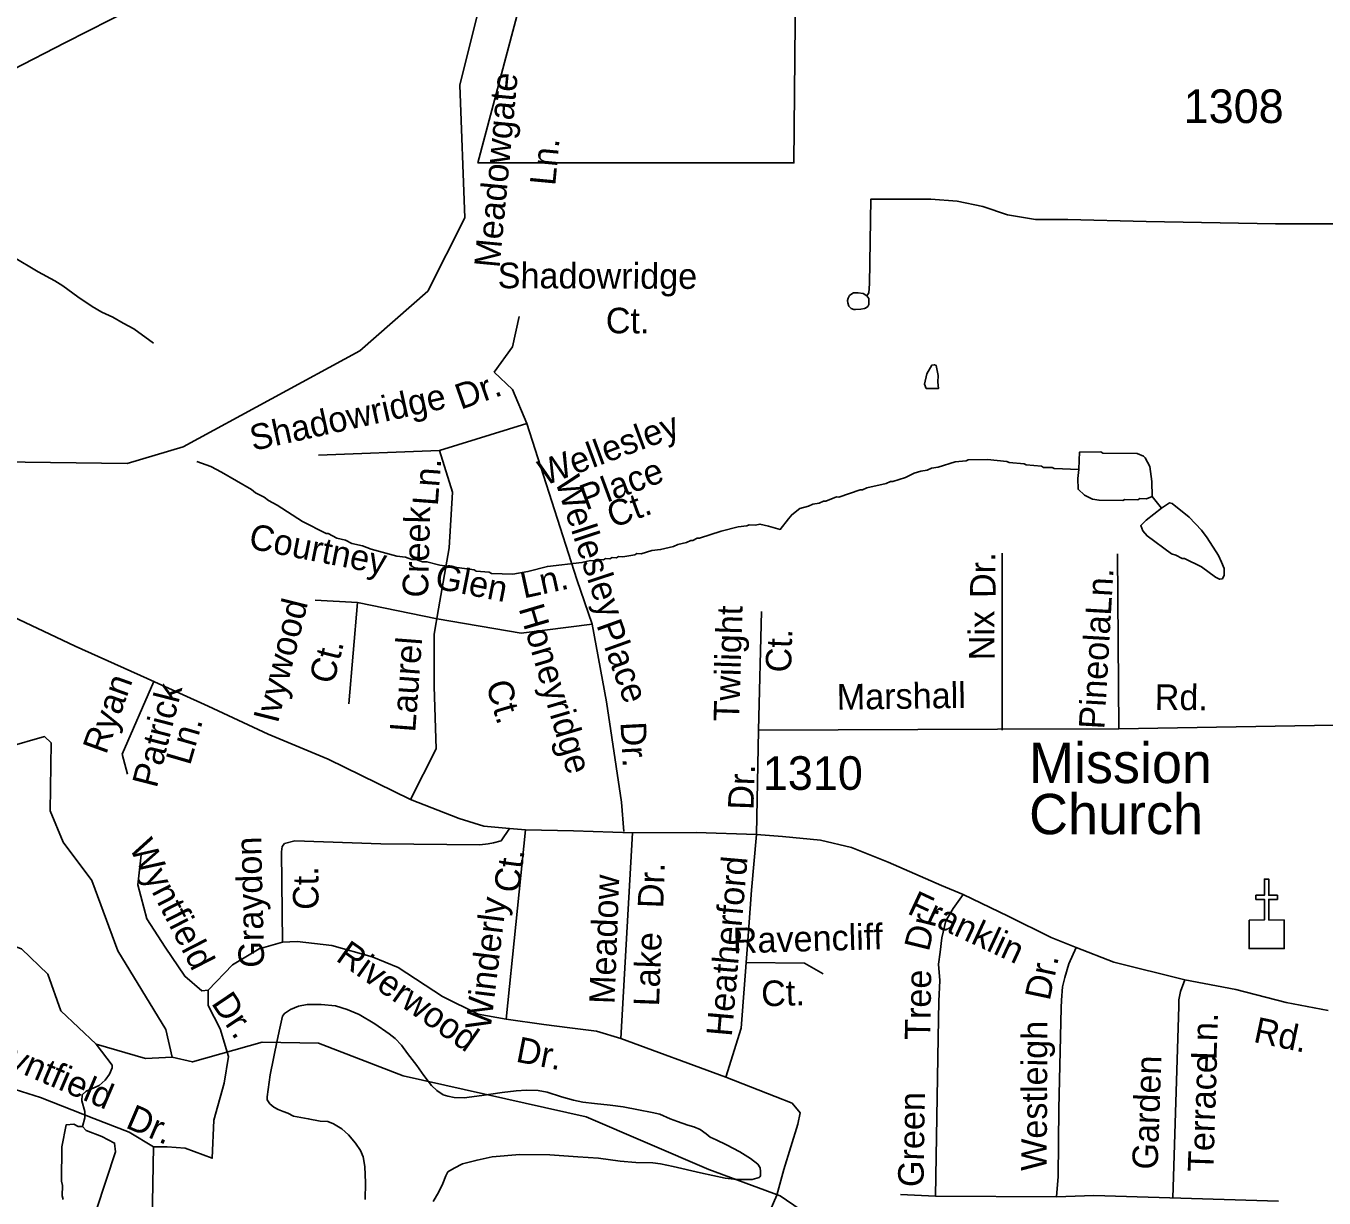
# Model space of a CAD drawing. Extents: x 1547597 to 1699558, y 810033 to 920809.
# Drawn here: x 1580417 to 1585242, y 862123 to 866479 of the extents above; entities that cross this region are included whole.
import ezdxf

# ---------------------------------------------------------------- set-up
doc = ezdxf.new("R2010")
doc.units = 0
for name, color, linetype in [('Exist Boundary Political City Limit New Hole', 7, 'Continuous'), ('Exist Cultural Church CELL', 7, 'Continuous'), ('Exist Cultural Church Label', 7, 'Continuous'), ('Exist Hydrographic Creek Single Shore', 7, 'Continuous'), ('Exist Hydrographic Misc Water Feature', 7, 'Continuous'), ('Exist Hydrographic Pond Under 1500 Sq Ft', 7, 'Continuous'), ('Exist Road Non-System Type 51', 7, 'Continuous'), ('Exist Road Non-System Type 51 Label', 7, 'Continuous'), ('Exist Road Secondary Type 51 Attributed', 7, 'Continuous'), ('Exist Road Secondary Type 51 Label', 7, 'Continuous'), ('Exist Road Secondary Type 51 Number Label', 7, 'Continuous')]:
    doc.layers.add(name, color=color, linetype=linetype)

msp = doc.modelspace()

# ---------------------------------------------------------------- linework, layer by layer
at = {"layer": 'Exist Boundary Political City Limit New Hole'}
msp.add_lwpolyline([(1583517.5, 866753.2), (1583718.2, 867614.8), (1582814.9, 868112.4), (1582523, 867797.8), (1582463.1, 867408.2), (1582530.5, 867385.8), (1582530.5, 867333.3), (1582515.5, 867265.9), (1582463.1, 867235.9), (1582418.2, 867183.5), (1582096.3, 865969.9), (1583271.4, 865969.9), (1583277.9, 866753.2), (1583517.5, 866753.2)], dxfattribs=at)
at = {"layer": 'Exist Cultural Church CELL'}
msp.add_lwpolyline([(1584963.4, 863156.3), (1585020.4, 863156.4), (1585020.4, 863232.6), (1584988.4, 863232.6), (1584988.4, 863248.5), (1585020.4, 863248.5), (1585020.4, 863308.7), (1585036.4, 863308.7), (1585036.4, 863248.5), (1585068.4, 863248.5), (1585068.4, 863232.6), (1585036.4, 863232.6), (1585036.4, 863156.4), (1585094.1, 863156.3), (1585094.1, 863049.8), (1584963.4, 863049.8)], close=True, dxfattribs=at)
at = {"layer": 'Exist Hydrographic Creek Single Shore'}
msp.add_lwpolyline([(1579810.6, 865007.4), (1580317.5, 864859.2), (1580792.5, 864852.9), (1581001.5, 864914.3), (1581657.6, 865271.9), (1581910.5, 865493.4), (1582047.6, 865766.4), (1582029.5, 866259.1), (1582100.5, 866543.2), (1582328.5, 866722.6), (1582521.5, 866810.5), (1582798.6, 866932.9), (1583185.5, 867210.7), (1583297.4, 867418.6)], dxfattribs=at)
at = {"layer": 'Exist Hydrographic Misc Water Feature'}
msp.add_line((1584637.3, 864686.5), (1584602.6, 864730.5), dxfattribs=at)
for points in [[(1583763.4, 865132), (1583794.4, 865131.7), (1583808.6, 865131.5), (1583806.7, 865155.4), (1583807, 865179.4), (1583799.4, 865217.6), (1583793.5, 865219.6), (1583783.4, 865217.8), (1583765.1, 865186), (1583756.7, 865148.2), (1583763.4, 865132)], [(1584602.6, 864730.5), (1584602.2, 864785.6), (1584594.8, 864841.7), (1584577.2, 864873.9), (1584571.3, 864880), (1584547.5, 864890.3), (1584419.5, 864891.8), (1584411.5, 864895.9), (1584332.2, 864894.8), (1584331.1, 864865), (1584330.1, 864830.6)], [(1584330.1, 864830.6), (1584238.9, 864834.2), (1584230.9, 864838.2), (1584198.9, 864838.6), (1584191, 864842.7), (1584135, 864847.5), (1584127.1, 864851.6), (1584071.1, 864856.3), (1584063.1, 864860.4), (1583991.3, 864867.2), (1583919.3, 864866.2), (1583911.2, 864862.3), (1583871.2, 864858.8), (1583807, 864839.7), (1583782.9, 864835.9), (1583766.8, 864828.1), (1583742.8, 864824.4), (1583718.7, 864816.7), (1583686.5, 864801.1), (1583638.4, 864785.7), (1583630.4, 864785.8), (1583614.3, 864778), (1583542.1, 864763), (1583526, 864755.2), (1583518, 864755.3), (1583437.7, 864728.3), (1583429.7, 864728.4), (1583389.5, 864712.9), (1583381.5, 864713), (1583365.4, 864705.3), (1583341.4, 864701.6), (1583325.3, 864693.8), (1583293.3, 864686.2), (1583263, 864662.5), (1583250.8, 864646.7), (1583220.5, 864608.1), (1583176.5, 864619.6), (1583144.6, 864628), (1583128.6, 864624.3), (1583104.6, 864624.6), (1583096.5, 864620.7), (1583064.5, 864617.1), (1583000.3, 864601.9), (1582920, 864574.9), (1582912, 864574.9), (1582896, 864567.1), (1582888, 864567.3), (1582871.9, 864559.5), (1582839.8, 864551.9), (1582823.7, 864544.1), (1582775.5, 864532.7), (1582743.5, 864529.1), (1582703.3, 864517.6), (1582687.3, 864517.8), (1582679.3, 864513.9), (1582635.2, 864506.5), (1582619.3, 864506.7), (1582611.3, 864502.8), (1582595.3, 864503), (1582587.2, 864499.1), (1582571.2, 864499.3), (1582563.2, 864495.4), (1582547.2, 864495.6), (1582539.1, 864491.7), (1582515.1, 864492), (1582483, 864484.4), (1582354.8, 864470.1), (1582282.7, 864451), (1582226.6, 864441.7), (1582146.6, 864444.6), (1582138.7, 864448.7), (1582090.7, 864453.3), (1582082.7, 864457.4), (1581955, 864475.1), (1581907.2, 864487.7), (1581891.2, 864487.9), (1581867.3, 864496.2), (1581851.3, 864496.4), (1581827.3, 864504.7), (1581795.5, 864509.1), (1581699.8, 864534.2), (1581667.9, 864546.6), (1581628, 864555.2), (1581604.1, 864567.5), (1581572.3, 864575.9), (1581540.5, 864592.3), (1581532.5, 864592.4), (1581445, 864637.4), (1581349.8, 864698.6), (1581318, 864715), (1581302.1, 864727.2), (1581270.3, 864743.6), (1581254.5, 864755.8), (1581143.3, 864821.1), (1581103.5, 864841.6), (1581051.4, 864860.3)], [(1584330.1, 864830.6), (1584326.4, 864797.1), (1584327.8, 864757.1), (1584351.6, 864734.8), (1584381.5, 864720.4), (1584405.4, 864716.1), (1584493.3, 864715), (1584501.4, 864718.9), (1584549.4, 864718.3), (1584557.4, 864722.2), (1584581.4, 864722), (1584602.6, 864730.5)], [(1584637.3, 864686.5), (1584667.2, 864706.8), (1584677.2, 864704.7), (1584740.6, 864654), (1584786, 864605.4), (1584807.7, 864577.1), (1584848.9, 864510.7), (1584860.6, 864486.5), (1584870.3, 864462.4), (1584870, 864438.4), (1584863.9, 864424.5), (1584853.8, 864422.6), (1584837.9, 864430.8), (1584786.3, 864469.4), (1584722.8, 864500.2), (1584714.8, 864500.3), (1584690.9, 864512.6), (1584675, 864516.8), (1584583.8, 864584), (1584568, 864602.1), (1584560.3, 864622.2), (1584580.5, 864642), (1584637.3, 864686.5)], [(1581350.6, 862708.5), (1581360.1, 862754.5), (1581370, 862799.4), (1581377.1, 862809.2), (1581399.4, 862823.9), (1581429.7, 862836.4), (1581461.8, 862841.8), (1581514, 862841.8), (1581567, 862836.9), (1581610.9, 862824.1), (1581655.7, 862805.2), (1581713.2, 862770.1), (1581766.7, 862733.1), (1581788.5, 862715.6), (1581812.1, 862691.1), (1581834.6, 862659.7), (1581870, 862616), (1581895.4, 862578.5), (1581923.8, 862540.8), (1581944.5, 862522.4), (1581967.3, 862507), (1581984.3, 862501.7), (1582008.2, 862497.1), (1582045.3, 862495.5), (1582110.6, 862504.3), (1582187, 862515), (1582239.2, 862521), (1582277.3, 862523.4), (1582320.4, 862522.6), (1582354.4, 862517), (1582407.2, 862499), (1582452.1, 862487.2), (1582487.1, 862479.5), (1582530.1, 862474.7), (1582588.1, 862468.6), (1582637.1, 862461.8), (1582694.1, 862450.7), (1582744, 862440.8), (1582772.9, 862434.3), (1582810.8, 862417.6), (1582838.7, 862407), (1582877.5, 862394.3), (1582899.5, 862387.9), (1582923.3, 862377.4), (1582945.1, 862362), (1582959.9, 862349.7), (1582982.8, 862339.3), (1583020.5, 862320.5), (1583070.3, 862294.6), (1583109.9, 862269.8), (1583137.6, 862248.3), (1583145.4, 862235.1), (1583147.2, 862222.1), (1583146.9, 862205.1), (1583144.2, 862201.9)], [(1581678, 862117.3), (1581678.1, 862179.4), (1581676.1, 862240.6), (1581669.7, 862275.8), (1581660, 862300.1), (1581641.5, 862327.5), (1581615.9, 862358), (1581590.3, 862380.5), (1581559.5, 862399), (1581538.6, 862407.4), (1581509.6, 862409), (1581465.6, 862417.8), (1581411.6, 862426.8), (1581389.8, 862438.2), (1581372.8, 862444.6), (1581354, 862451.9), (1581338.1, 862460.2), (1581323.2, 862473.5), (1581313.5, 862487.7), (1581312.7, 862498.8), (1581324, 862580.7), (1581350.6, 862708.5)], [(1580626.5, 862388.7), (1580634.9, 862420.6), (1580635.2, 862444.6), (1580623.7, 862484.6), (1580625.9, 862506.7), (1580640.1, 862520.4), (1580688.3, 862541.8), (1580710.5, 862561.5), (1580726.8, 862583.4), (1580737.1, 862607.2), (1580737.2, 862617.2), (1580677.5, 862695.2)], [(1584715.5, 861769.6), (1584351.5, 861957.6), (1584177.5, 861993.9), (1584026.5, 861960.8), (1583951.6, 861919.7), (1583866.6, 861806.5), (1583773.5, 861765.7), (1583533.6, 861842.8), (1583400.5, 861911.1), (1583294.5, 862080.7), (1583220.6, 862131.4), (1582955.5, 862228.8), (1582499.5, 862425.2), (1581818.5, 862576.9), (1581503.6, 862698.1), (1581294.5, 862702.4), (1581035.5, 862628.8), (1580960.5, 862646.7)], [(1580555.3, 862117.7), (1580551.5, 862131.7), (1580551.9, 862169.7), (1580548.1, 862185.8), (1580549.7, 862313.7), (1580565.9, 862394.8), (1580594.6, 862397.1), (1580610.5, 862388.9), (1580626.5, 862388.7)], [(1580626.5, 862388.7), (1580640.3, 862374.5), (1580698, 862351.8), (1580745.8, 862327.3), (1580749.4, 862295.2), (1580678.8, 862080.2)], [(1583144.2, 862201.9), (1583141.8, 862199.1), (1583116.6, 862192.5), (1583059.5, 862192.5), (1583015.4, 862197.4), (1582923.5, 862217), (1582822.8, 862239.9), (1582775.8, 862249.8), (1582746.8, 862254.4), (1582683.6, 862255.5), (1582625.6, 862259.5), (1582544.6, 862271), (1582468.5, 862276.4), (1582363.4, 862283.3), (1582252.2, 862284.3), (1582149.8, 862276.2), (1582093.5, 862264.1), (1582039.1, 862250.1), (1582008.7, 862234.6), (1581984.4, 862220), (1581977.1, 862206.1), (1581965.6, 862177.3), (1581950.1, 862143.4), (1581930.4, 862109.7)]]:
    msp.add_lwpolyline(points, dxfattribs=at)
at = {"layer": 'Exist Hydrographic Pond Under 1500 Sq Ft'}
for points in [[(1580960.5, 862646.7), (1580936.5, 862749), (1580757.5, 863041.5), (1580661.5, 863302.8), (1580555.5, 863446.1), (1580506.5, 863562), (1580510.5, 863814.7), (1580485.5, 863838.2), (1580209.5, 863758.4), (1580101.5, 863770.4)], [(1580960.5, 862646.7), (1580860.5, 862642.2), (1580677.5, 862695.2), (1580545.6, 862819.3), (1580497.5, 862954.9), (1580399.5, 863048.7), (1580142.5, 863142.7), (1580085.5, 863219.2), (1580060.5, 863278.9), (1580137.5, 863385.6), (1580129.5, 863451.5), (1580014.5, 863562.2), (1580007.5, 863627.9), (1580101.5, 863770.4)]]:
    msp.add_lwpolyline(points, dxfattribs=at)
at = {"layer": 'Exist Road Non-System Type 51'}
for p, q in [((1582249.7, 865399.7), (1582225.3, 865286.1)), ((1582225.3, 865286.1), (1582156.4, 865192.8)), ((1582156.4, 865192.8), (1582225.3, 865127.8)), ((1582225.3, 865127.8), (1582278.1, 865002)), ((1582278.1, 865002), (1581953.6, 864900.6)), ((1582278.1, 865002), (1582464.6, 864421.7)), ((1581953.6, 864900.6), (1581503.5, 864884.4)), ((1581953.6, 864900.6), (1582002.3, 864746.4)), ((1582002.3, 864746.4), (1581990.1, 864539.4)), ((1581990.1, 864539.4), (1581949.6, 864312.2)), ((1584045.2, 863862.2), (1584045.9, 864519.2)), ((1584479.6, 863867.1), (1584473.5, 864517.1)), ((1582464.6, 864421.7), (1582521.4, 864255.3)), ((1581491.3, 864344.6), (1581649.5, 864336.5)), ((1581649.5, 864336.5), (1581617, 863959.1)), ((1581649.5, 864336.5), (1581945.5, 864275.6)), ((1581949.6, 864312.2), (1581933.4, 864218.8)), ((1583139.9, 863862.1), (1583150.3, 864302.7)), ((1581945.5, 864275.6), (1582257.8, 864222.9)), ((1582257.8, 864222.9), (1582521.4, 864255.3)), ((1582521.4, 864255.3), (1582574.1, 863967.2)), ((1581933.4, 864218.8), (1581933.4, 864024)), ((1580774.4, 863772.9), (1580892.1, 864042.6)), ((1581933.4, 864024), (1581941.5, 863792.7)), ((1583139.9, 863862.1), (1583131.9, 863474.6)), ((1584027.5, 863865.1), (1583139.9, 863862.1)), ((1584479.6, 863867.1), (1584027.5, 863865.1)), ((1585460.3, 863883.8), (1584479.6, 863867.1)), ((1580794.6, 863698.8), (1580774.4, 863772.9)), ((1581941.5, 863792.7), (1581846.2, 863604.5)), ((1582273.1, 863491.8), (1582201, 862788.4)), ((1582670.9, 863480.5), (1582627.6, 862716.3)), ((1581368.9, 863429.4), (1581366.6, 863409.2)), ((1581377.8, 863440.6), (1581368.9, 863429.4)), ((1581416.1, 863450.1), (1581377.8, 863440.6)), ((1581366.6, 863409.2), (1581370.1, 863073.5)), ((1583093.5, 862998.4), (1583310.7, 862996.1)), ((1583310.7, 862996.1), (1583380.3, 862955.7)), ((1584724.7, 862933.8), (1584708.8, 862890.6)), ((1584708.8, 862890.6), (1584702, 862859.2)), ((1584702, 862859.2), (1584702, 862834.5)), ((1584702, 862834.5), (1584679.4, 862123.4)), ((1583797.5, 862129.6), (1583667, 862135.6)), ((1583797.5, 862129.6), (1584247.6, 862127.8)), ((1584247.6, 862127.8), (1584385.5, 862132.2)), ((1584385.5, 862132.2), (1585072.2, 862111.6))]:
    msp.add_line(p, q, dxfattribs=at)
for points in [[(1579897.7, 865963.2), (1579919.4, 865937), (1579939.2, 865916.5), (1579982.5, 865884), (1580061.7, 865822.8), (1580152.9, 865759.5), (1580212.4, 865722.5), (1580258, 865694), (1580277.7, 865679.6), (1580291.5, 865667.5), (1580315.5, 865655), (1580367, 865622.3), (1580462.1, 865565), (1580523.7, 865532.1), (1580553.5, 865513.5), (1580608.9, 865472.7), (1580662.4, 865436), (1580698.2, 865415.5), (1580739.9, 865396.8), (1580777.6, 865374.3), (1580817.3, 865353.7), (1580890.6, 865300.5)], [(1585400.1, 865730.2), (1585286.6, 865743.5), (1585061.8, 865743.5), (1584581.2, 865752.5), (1584289.7, 865759.1), (1584169.5, 865759.1), (1584064.9, 865776.9), (1583973.7, 865808.1), (1583878, 865828.2), (1583780.1, 865834.9), (1583556.7, 865834.8), (1583552.3, 865520.8), (1583550.1, 865487.4), (1583542.3, 865476.4)], [(1583550.3, 865466.2), (1583542.3, 865476.4), (1583528.4, 865484.4), (1583510.5, 865486.8), (1583492.5, 865487), (1583482.3, 865481.2), (1583478.3, 865477.2), (1583472.3, 865467.4), (1583470.1, 865459.2), (1583471.9, 865449.4), (1583475.9, 865437.3), (1583483.7, 865429.1), (1583493.6, 865424.9), (1583499.6, 865424.8), (1583519.7, 865426.6), (1583533.7, 865428.3), (1583537.7, 865430.2), (1583545.9, 865436.3), (1583549.8, 865444.2), (1583550.3, 865466.2)], [(1582574.1, 863967.2), (1582630.9, 863593.9), (1582639.2, 863485.7)], [(1581416.1, 863450.1), (1581736, 863439.4), (1582104.2, 863436.1), (1582134.3, 863439.7), (1582154.3, 863443.5), (1582182.5, 863450.9), (1582213.8, 863496.2)], [(1583131.9, 863474.6), (1583113.3, 863267.7), (1583098.5, 863063), (1583074.8, 862754.4), (1583018, 862572)], [(1580844.5, 863398.2), (1580832.5, 863286.9), (1580865.5, 863160.7), (1580934.6, 863055.5), (1581006.7, 862947.2), (1581069.8, 862893.1), (1581093.8, 862896.1)], [(1583900.1, 863250.9), (1583862.6, 863198.8), (1583835.9, 863152.8), (1583821.1, 863090.5), (1583815.1, 863037.1), (1583809.2, 862992.6), (1583813.1, 862931.1), (1583809.9, 862855.1), (1583807.8, 862717.8), (1583797.5, 862129.6)], [(1581370.1, 863073.5), (1581283, 863049.4), (1581183.9, 862989.3), (1581093.8, 862896.1)], [(1582201, 862788.4), (1582097, 862806), (1581964.9, 862872.1), (1581799.7, 862980.3), (1581703.6, 863019.4), (1581553.4, 863061.5), (1581424.2, 863076.5), (1581370.1, 863073.5)], [(1584247.6, 862127.8), (1584253.6, 862203.5), (1584256.5, 862454.2), (1584265.2, 862830.1), (1584265.5, 862858.1), (1584269.8, 862908.3), (1584278.1, 862942.1), (1584293.5, 862993.1), (1584320.1, 863054)], [(1581093.8, 862896.1), (1581093.8, 862839), (1581138.9, 862751.8), (1581168.9, 862649.6), (1581153.9, 862550.4), (1581114.8, 862412.2), (1581108.8, 862270.9), (1581007.9, 862307.8), (1580941.8, 862313.8), (1580890.8, 862313.8)], [(1582201, 862788.4), (1582342.2, 862767.4), (1582438.3, 862755.4), (1582537.4, 862743.3), (1582627.6, 862716.3)], [(1582627.6, 862716.3), (1583018, 862572)], [(1583018, 862572), (1583201.3, 862499.8), (1583264.3, 862475.8), (1583294.4, 862439.7), (1583285.4, 862397.6), (1583234.3, 862229.3), (1583207.3, 862133.1), (1583162.2, 862027.9), (1583069.1, 861862.6), (1583003, 861775.4)], [(1580890.8, 862313.8), (1580800.6, 862367.9), (1580668.5, 862419), (1580470.2, 862497.2), (1580305, 862548.3), (1580190.9, 862557.3)], [(1580890.8, 862313.8), (1580884.7, 861968.1), (1581237.5, 861945.3)]]:
    msp.add_lwpolyline(points, dxfattribs=at)
at = {"layer": 'Exist Road Secondary Type 51 Attributed'}
for points in [[(1581088.6, 866730), (1581067.5, 866687.3), (1581046.7, 866665), (1580997.8, 866633.8), (1580812.5, 866543.3), (1580563.5, 866417.2), (1580366.8, 866315.8), (1580193.4, 866217.8), (1580067.4, 866137.7), (1579990.3, 866075.4), (1579857.4, 865954.4), (1579768.5, 865841.6), (1579678.1, 865718.5), (1579604.9, 865615.3), (1579509.2, 865442), (1579410.1, 865269.2), (1579300.4, 865077.8), (1579168.5, 864847)], [(1585257.6, 862819.8), (1585100.5, 862849.5), (1584914.5, 862898.2), (1584724.7, 862933.8), (1584460.9, 862999.1), (1584320.1, 863054), (1584227.7, 863090.7), (1584067.6, 863170.8), (1583900.1, 863250.9), (1583820.1, 863285), (1583621.5, 863371.1), (1583485.1, 863426), (1583369.5, 863452.7), (1583228.3, 863467.1), (1583131.9, 863474.6), (1582908.1, 863482), (1582670.9, 863480.5), (1582452.4, 863487.3), (1582273.1, 863491.8), (1582213.8, 863496.2), (1582118.9, 863505.1), (1582027, 863533.3), (1581846.2, 863604.5), (1581540.3, 863754), (1581316.5, 863847.4), (1581094.1, 863951.3), (1580866.6, 864054.1), (1580599.8, 864174.3), (1580318.2, 864306.3)]]:
    msp.add_lwpolyline(points, dxfattribs=at)

# ---------------------------------------------------------------- texts
at = {"layer": 'Exist Cultural Church Label'}
for s, p in [('Mission ', (1584145.3, 863665.1)), ('Church', (1584145.3, 863475.1))]:
    msp.add_text(s, height=150, dxfattribs=at).set_placement(p)
at = {"layer": 'Exist Road Non-System Type 51 Label'}
for s, rotation, p in [('Meadowgate', 84.6144, (1582177, 865577.5)), ('Ln.', 84.6144, (1582383.8, 865883.1)), ('Shadowridge', 359.7839, (1582169.9, 865504.4)), ('Ct.', 359.7839, (1582571.8, 865336.8)), ('Dr.', 19.3359, (1582032.6, 865052.3)), ('Shadowridge', 12.4585, (1581260.2, 864899.4)), ('Wellesley', 20.3364, (1582343.6, 864769.2)), ('Ln.', 85.7352, (1581947.4, 864693.5)), ('Place', 20.3364, (1582497.4, 864677.9)), ('Wellesley', 288.2796, (1582382.2, 864788.7)), ('Ct.', 20.3364, (1582598, 864611.8)), ('Creek', 88.5322, (1581910.9, 864353.6)), ('Courtney', 348.8709, (1581240.7, 864538)), ('Dr.', 90.5323, (1584021.3, 864353.4)), ('Glen', 348.8709, (1581932.5, 864389.3)), ('Ln.', 12.3165, (1582266.7, 864351)), ('Ln.', 86.7013, (1584449.4, 864286.2)), ('Ivywood', 75.9732, (1581352.7, 863883.9)), ('Honeyridge', 286.4294, (1582247.3, 864314.4)), ('Twilight', 88.2236, (1583067.2, 863892.6)), ('Nix', 90.5323, (1584017.4, 864122.1)), ('Place', 289.7339, (1582536, 864252.9)), ('Pineola', 86.7013, (1584424.9, 863863.6)), ('Laurel', 85.7352, (1581863.4, 863852.1)), ('Ct.', 88.2236, (1583260.4, 864075.1)), ('Ct.', 75.9732, (1581560, 864029.1)), ('Ryan', 70.3005, (1580714.5, 863768.4)), ('Patrick', 75.654, (1580902.3, 863643.6)), ('Ct.', 286.4294, (1582125.4, 864032.9)), ('Marshall', 0.8428, (1583431, 863937.7)), ('Rd.', 359.6662, (1584612.2, 863937.1)), ('Ln.', 73.9094, (1581026.3, 863727.9)), ('Dr.', 272.9873, (1582626.4, 863891)), ('Dr.', 87.988, (1583120.8, 863564.7)), ('Wyntfield', 297.166, (1580798.7, 863426.6)), ('Graydon', 91.3884, (1581302.5, 862980)), ('Ct.', 82.4173, (1582249.2, 863253.9)), ('Heatherford', 84.9171, (1583040.1, 862720.9)), ('Ct.', 90.1456, (1581504.2, 863194.1)), ('Dr.', 87.8769, (1582785.3, 863198.8)), ('Meadow', 87.8769, (1582604.7, 862842.7)), ('Winderly', 83.0201, (1582143.2, 862744.7)), ('Dr.', 76.2732, (1583772.3, 863036.1)), ('Ravencliff', 1.6196, (1583045.3, 863032.1)), ('Lake', 87.8769, (1582769.8, 862834.2)), ('Riverwood', 324.7897, (1581564.5, 863008)), ('Dr.', 78.1336, (1584221.8, 862853.5)), ('Tree', 89.2062, (1583778.2, 862710.2)), ('Ct.', 1.6196, (1583150.7, 862835.1)), ('Dr.', 303.9307, (1581103.1, 862847)), ('Westleigh', 89.6888, (1584210.8, 862223.6)), ('Ln.', 88.0922, (1584841.8, 862634.3)), ('Wyntfield', 336.8053, (1580234.4, 862656.2)), ('Dr.', 348.905, (1582234, 862630.4)), ('Garden', 88.0922, (1584623.2, 862227.6)), ('Terrace', 88.0922, (1584830, 862218.7)), ('Dr.', 336.8053, (1580782.8, 862386.2)), ('Green', 89.1637, (1583753, 862163.2))]:
    msp.add_text(s, height=95, rotation=rotation, dxfattribs=at).set_placement(p)
at = {"layer": 'Exist Road Secondary Type 51 Label'}
for s, rotation, p in [('Franklin', 335.0278, (1583688.5, 863181.9)), ('Rd.', 348.1255, (1584975.8, 862703.7))]:
    msp.add_text(s, height=95, rotation=rotation, dxfattribs=at).set_placement(p)
at = {"layer": 'Exist Road Secondary Type 51 Number Label'}
for s, p in [('1308', (1584720, 866118.1)), ('1310', (1583155.6, 863640))]:
    msp.add_text(s, height=125, dxfattribs=at).set_placement(p)

doc.saveas('drawing.dxf')
